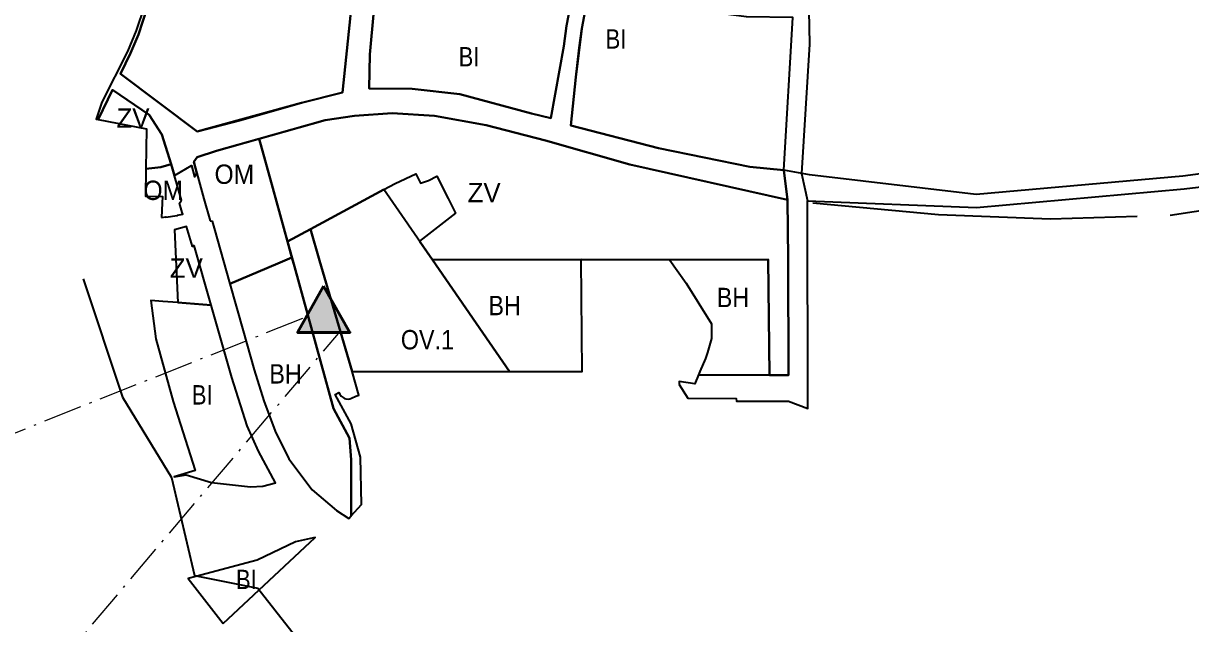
# Model space of a CAD drawing. Extents: x -650276 to -642489, y -1074311 to -1066658.
# Drawn here: x -645941 to -645218, y -1070271 to -1069899 of the extents above; entities that cross this region are included whole.
import ezdxf

# ---------------------------------------------------------------- set-up
doc = ezdxf.new("R2010")
doc.units = 0
doc.header["$LTSCALE"] = 4.8
doc.linetypes.add('DOT_DASHED', pattern=[7.7, 5, -1.2, 0.3, -1.2])
for name, color, linetype, lineweight in [('1', 7, 'Continuous', 35), ('11', 7, 'Continuous', 35), ('12', 7, 'Continuous', 35), ('15', 7, 'Continuous', 35), ('2', 7, 'Continuous', 35), ('40', 7, 'Continuous', 35), ('54', 7, 'Continuous', 35), ('55', 7, 'Continuous', 53)]:
    doc.layers.add(name, color=color, linetype=linetype, lineweight=lineweight)
doc.layers.add('62', color=7, linetype='Continuous')

msp = doc.modelspace()

# ---------------------------------------------------------------- hatches: boundary and pattern name
at = {"layer": '55'}
msp.add_hatch(color=256, dxfattribs=at).paths.add_polyline_path([(-645754.857, -1070061.969), (-645770.808, -1070090.615), (-645738.424, -1070090.615)])

# ---------------------------------------------------------------- linework, layer by layer
at = {"layer": '1'}
for points in [[(-645772.853, -1070049.868), (-645774.423, -1070044.167), (-645783.063, -1070047.855), (-645812.76, -1070060.53)], [(-645737.756, -1070204.389), (-645737.624, -1070169.544), (-645738.79, -1070156.281), (-645748.62, -1070137.889), (-645772.853, -1070049.868)], [(-645812.76, -1070060.53), (-645804.52, -1070089.63), (-645797.66, -1070113.88), (-645791.72, -1070133.09), (-645784.83, -1070151.9), (-645784.83, -1070151.9)], [(-645784.83, -1070151.9), (-645776.26, -1070168.94), (-645761.78, -1070188.29), (-645746.73, -1070201.04), (-645739.12, -1070205.9), (-645737.756, -1070204.389)]]:
    msp.add_lwpolyline(points, dxfattribs=at)
for points in [[(-645639.638, -1070114.895), (-645594.733, -1070114.868), (-645595.2, -1070045.403), (-645687.31, -1070045.724)], [(-645522.587, -1070116.952), (-645478.664, -1070117.114), (-645479.429, -1070045.409), (-645540.433, -1070045.752), (-645530.3, -1070060.08), (-645514.49, -1070085.4), (-645514.56, -1070090.91), (-645514.61, -1070094.35), (-645517.02, -1070103.08), (-645518.35, -1070106.87), (-645521.73, -1070114.83)]]:
    msp.add_lwpolyline(points, close=True, dxfattribs=at)
at = {"layer": '11'}
msp.add_lwpolyline([(-645639.638, -1070114.895), (-645687.31, -1070045.724), (-645717.36, -1070002.12), (-645762.868, -1070026.606), (-645757.215, -1070045.97), (-645737.075, -1070114.955)], close=True, dxfattribs=at)
at = {"layer": '12'}
for points in [[(-645794.679, -1069970.596), (-645821, -1069978), (-645833, -1069982), (-645835, -1069985), (-645833.32, -1069991.86)], [(-645777.143, -1070034.287), (-645786.238, -1070001.251), (-645794.679, -1069970.596)], [(-645833.32, -1069991.86), (-645828.9, -1070007.76), (-645825.08, -1070021.52)], [(-645825.08, -1070021.52), (-645823.76, -1070021.67), (-645822.549, -1070025.948), (-645812.76, -1070060.53), (-645783.063, -1070047.855), (-645774.423, -1070044.167), (-645777.143, -1070034.287)]]:
    msp.add_lwpolyline(points, dxfattribs=at)
msp.add_lwpolyline([(-645855.17, -1070019.44), (-645852.36, -1070019.01), (-645852.33, -1070019.2), (-645845.37, -1070018.12), (-645845.14, -1070018.08), (-645845.17, -1070017.91), (-645841.89, -1070017.42), (-645842.238, -1070016.251), (-645843.94, -1070010.6), (-645843, -1070009), (-645842.8, -1070008.59), (-645843.22, -1070007.12), (-645849.1, -1069986.42), (-645855.54, -1069988.24), (-645864.77, -1069989.26), (-645864.97, -1070006.16), (-645854.42, -1070006.47), (-645854.65, -1070010.44)], close=True, dxfattribs=at)
at = {"layer": '15'}
for points in [[(-645865.78, -1069888.76), (-645870.89, -1069903.5), (-645876.15, -1069916.47), (-645892.09, -1069947.98), (-645895.66, -1069958.42), (-645894.25, -1069958.7), (-645885.422, -1069940.184), (-645862.782, -1069955.809), (-645854.81, -1069967.927), (-645849.1, -1069986.42), (-645847.14, -1069993.34), (-645836.64, -1069987.18), (-645834.65, -1069994.21), (-645833.32, -1069991.86), (-645835, -1069985), (-645833, -1069982), (-645821, -1069978), (-645753.706, -1069959.071), (-645735.532, -1069956.306), (-645712.222, -1069954.725), (-645686.147, -1069956.306), (-645654.145, -1069962.232), (-645617.403, -1069971.714), (-645565.133, -1069986.508), (-645467.472, -1070008.38), (-645469.701, -1069990.011), (-645490.814, -1069988.074), (-645547.4, -1069976.382), (-645601.753, -1069962.317), (-645598.491, -1069932.472), (-645596.463, -1069914.335), (-645594.866, -1069902.242), (-645589.84, -1069875.892)], [(-645599.271, -1069873.685), (-645604.424, -1069900.701), (-645606.07, -1069913.163), (-645614.072, -1069957.797), (-645625.979, -1069954.92), (-645670.325, -1069943.002), (-645699.889, -1069939.714), (-645726.542, -1069939.398), (-645726.131, -1069918.457), (-645723.668, -1069891.356)], [(-645738.039, -1069894.231), (-645742.967, -1069941.862), (-645768.424, -1069948.431), (-645833, -1069966), (-645880.431, -1069930.3), (-645874.219, -1069917.496), (-645869.262, -1069905.935), (-645863.95, -1069889.468)], [(-645124.233, -1069980.695), (-645222.809, -1069993.701), (-645350.784, -1070005.227), (-645453.852, -1069992.968), (-645469.701, -1069990.011), (-645467.472, -1070008.38), (-645467.068, -1070044.959), (-645466.96, -1070117.157), (-645478.664, -1070117.114), (-645522.587, -1070116.952), (-645524.82, -1070122.48), (-645534.63, -1070121.09), (-645534.7, -1070122.95), (-645529.17, -1070131.4), (-645499.276, -1070131.652), (-645499.142, -1070133.293), (-645466.862, -1070133.219), (-645454.881, -1070137.836), (-645455.073, -1070009.111), (-645350.591, -1070013.242), (-645221.99, -1070001.66), (-645194.003, -1069998.417)], [(-645757.215, -1070045.97), (-645762.868, -1070026.606), (-645777.143, -1070034.287), (-645772.853, -1070049.868), (-645748.62, -1070137.889)], [(-645737.63, -1070147.39), (-645747.67, -1070129.14), (-645745.29, -1070127.83), (-645744.73, -1070129), (-645743.87, -1070130.15), (-645742.67, -1070131.07), (-645741.83, -1070131.53), (-645740.89, -1070131.8), (-645739.41, -1070131.93), (-645738.41, -1070131.78), (-645737.48, -1070131.45), (-645734.77, -1070130.18), (-645732.91, -1070129.5), (-645737.075, -1070114.955), (-645757.215, -1070045.97)], [(-645748.62, -1070137.889), (-645738.79, -1070156.281), (-645737.624, -1070169.544), (-645737.756, -1070204.389)], [(-645737.756, -1070204.389), (-645731.3, -1070197.24), (-645731.94, -1070167.87), (-645737.63, -1070147.39)]]:
    msp.add_lwpolyline(points, dxfattribs=at)
at = {"layer": '2'}
for points in [[(-645806, -1069959), (-645768.424, -1069948.431), (-645742.967, -1069941.862), (-645738.039, -1069894.231), (-645729.006, -1069844.136), (-645777.852, -1069832.241), (-645804.185, -1069825.84), (-645808.28, -1069865.39), (-645808.84, -1069870.75), (-645849.79, -1069868.4), (-645850.92, -1069863.41), (-645857.204, -1069862.954), (-645857.289, -1069863.338), (-645863.95, -1069889.468), (-645869.262, -1069905.935), (-645874.219, -1069917.496), (-645880.431, -1069930.3), (-645833, -1069966)], [(-645606.07, -1069913.163), (-645604.424, -1069900.701), (-645599.271, -1069873.685), (-645677.849, -1069855.3), (-645716.277, -1069847.01), (-645723.668, -1069891.356), (-645726.131, -1069918.457), (-645726.542, -1069939.398), (-645699.889, -1069939.714), (-645670.325, -1069943.002), (-645625.979, -1069954.92), (-645614.072, -1069957.797)], [(-645589.84, -1069875.892), (-645594.866, -1069902.242), (-645598.491, -1069932.472), (-645601.753, -1069962.317), (-645547.4, -1069976.382), (-645490.814, -1069988.074), (-645469.701, -1069990.011), (-645469.701, -1069990.011), (-645464.288, -1069895.362), (-645492.842, -1069895), (-645526.451, -1069890.745)], [(-645792.37, -1070186.01), (-645784.51, -1070183.77), (-645795.07, -1070164.26), (-645801.99, -1070148.51), (-645811.48, -1070118.65), (-645824.28, -1070073.67), (-645845.01, -1070072.12), (-645854.25, -1070071.4), (-645861.74, -1070070.95), (-645858.53, -1070094.64), (-645847.88, -1070133.4), (-645834.31, -1070176.15), (-645847.2, -1070180.14), (-645839.82, -1070178.94), (-645824.12, -1070183.63), (-645799.91, -1070186.32)], [(-645816.9, -1070270.96), (-645760.05, -1070217.79), (-645760.91, -1070217.98), (-645772.08, -1070220.39), (-645795.85, -1070231.81), (-645833.92, -1070241.96), (-645838.53, -1070243.19)]]:
    msp.add_lwpolyline(points, close=True, dxfattribs=at)
at = {"layer": '40'}
for points in [[(-645849.1, -1069986.42), (-645854.81, -1069967.927), (-645862.782, -1069955.809), (-645885.422, -1069940.184), (-645894.25, -1069958.7), (-645864.48, -1069964.53), (-645864.77, -1069989.26), (-645855.54, -1069988.24)], [(-645595.2, -1070045.403), (-645479.429, -1070045.409), (-645478.664, -1070117.114), (-645466.96, -1070117.157), (-645467.068, -1070044.959), (-645467.472, -1070008.38), (-645565.133, -1069986.508), (-645617.403, -1069971.714), (-645654.145, -1069962.232), (-645686.147, -1069956.306), (-645712.222, -1069954.725), (-645735.532, -1069956.306), (-645753.706, -1069959.071), (-645794.679, -1069970.596), (-645786.238, -1070001.251), (-645777.143, -1070034.287), (-645762.868, -1070026.606), (-645717.36, -1070002.12), (-645710.43, -1069998.39), (-645697.59, -1069992.31), (-645694.8, -1069998.22), (-645689.84, -1069996.37), (-645684.59, -1069993.87), (-645677.65, -1070007.66), (-645677.02, -1070008.93), (-645675.24, -1070012.51), (-645673.1, -1070016.78), (-645695.39, -1070034), (-645687.31, -1070045.724)], [(-645834.8, -1070036.71), (-645835.91, -1070037.31), (-645839.64, -1070024.9), (-645847.08, -1070027.09), (-645845.01, -1070072.12), (-645824.28, -1070073.67), (-645824.28, -1070073.67)]]:
    msp.add_lwpolyline(points, close=True, dxfattribs=at)
at = {"layer": '54'}
for points in [[(-645624.473, -1069340.207), (-645597.606, -1069359.137), (-645542.894, -1069403.796), (-645505.738, -1069437.197), (-645484.202, -1069466.216), (-645467.655, -1069503.794), (-645460.072, -1069535.704), (-645458, -1069561.601), (-645458, -1069658.925), (-645456, -1069668), (-645455.002, -1069859.825), (-645453.95, -1069912.05), (-645458.804, -1069992.044), (-645455.073, -1070009.111)], [(-645230.538, -1070017.864), (-644946.741, -1069974.541), (-644816.387, -1069962.572), (-644667.646, -1069930.034), (-644586.303, -1069905.244), (-644248.286, -1069794.155), (-644097.378, -1069760.147), (-643995.653, -1069721.915)], [(-645451.854, -1070010.265), (-645374.117, -1070017.569), (-645304.693, -1070020.185), (-645251.015, -1070018.538)], [(-645903.547, -1070057.381), (-645879.191, -1070130.665), (-645848.973, -1070180.543), (-645834.684, -1070241.324), (-645795.429, -1070249.201), (-645711.259, -1070356.569)]]:
    msp.add_lwpolyline(points, dxfattribs=at)
at = {"layer": '55', "linetype": 'DOT_DASHED', "lineweight": 25}
for p, q in [((-647060.176, -1070597.455), (-645765.418, -1070080.935)), ((-646590, -1071090), (-645744.292, -1070089.84))]:
    msp.add_line(p, q, dxfattribs=at)
at = {"layer": '55'}
msp.add_lwpolyline([(-645754.857, -1070061.969), (-645770.808, -1070090.615), (-645738.424, -1070090.615)], close=True, dxfattribs=at)

# ---------------------------------------------------------------- texts
at = {"layer": '62'}
for s, width, p in [('BI', 0.85, (-645580.138, -1069914.734)), ('BI', 0.85, (-645671.138, -1069925.734)), ('OM', 0.95, (-645822.28, -1069998.561)), ('OM', 0.95, (-645866.28, -1070008.561)), ('BH', 0.9, (-645511.328, -1070074.977)), ('BH', 0.9, (-645652.699, -1070079.977)), ('OV.1', 0.9, (-645706.926, -1070101.134)), ('BH', 0.9, (-645788.337, -1070122.32)), ('BI', 0.85, (-645836.337, -1070135.32)), ('BI', 0.85, (-645808.987, -1070249.726))]:
    msp.add_text(s, height=12, dxfattribs=dict(at, width=width)).set_placement(p)
for p in [(-645883.022, -1069963.776), (-645665.601, -1070009.978), (-645850.022, -1070056.776)]:
    msp.add_text('ZV', height=12, dxfattribs=at).set_placement(p)

doc.saveas('drawing.dxf')
